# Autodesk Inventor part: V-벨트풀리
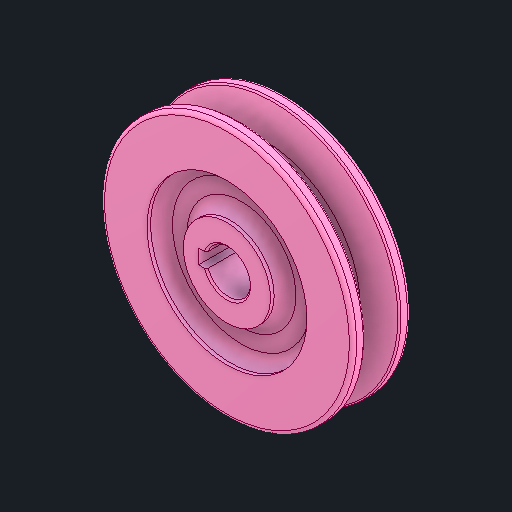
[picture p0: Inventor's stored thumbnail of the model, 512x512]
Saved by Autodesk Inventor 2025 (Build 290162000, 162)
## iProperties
Created: 2025-08
Part Number: V-벨트풀리
Material: 강철, 연강
Document SubType Name: Modeling
Designer: infra012
Density: 7.86 g/cm^3
Appearance: 기본값
Author: jhkim
Sending System: Autodesk Inventor 2026
Preprocessor: ST-DEVELOPER v20.1
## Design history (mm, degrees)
sketch "스케치1"
  geometry: 1 further point
  constraints: 1 other
feature "Solid1"
node "솔리드1"
